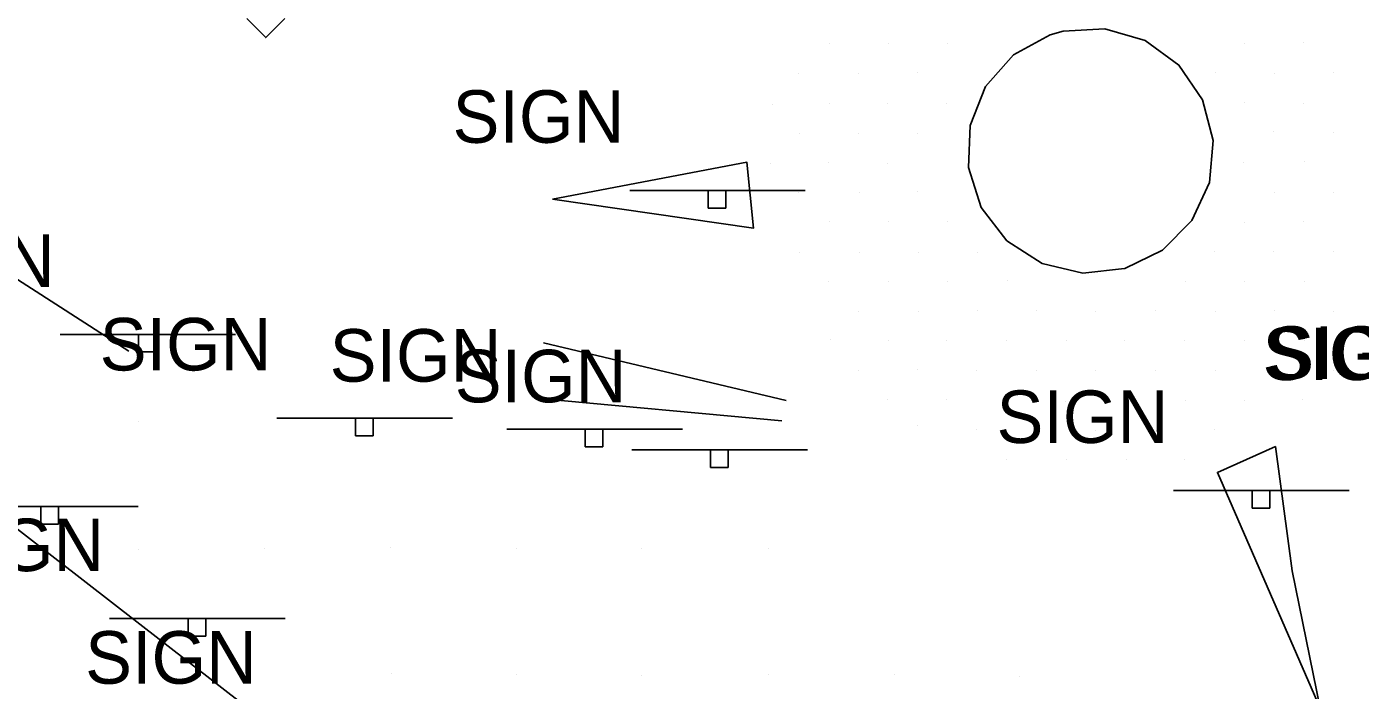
# Model space of a CAD drawing. Extents: x 1602514 to 1609837, y 863887 to 871157.
# Drawn here: x 1604719.6 to 1604878.4, y 866874 to 866952.9 of the extents above; entities that cross this region are included whole.
import ezdxf

# ---------------------------------------------------------------- set-up
doc = ezdxf.new("R2010")
doc.units = 0
for name, color, linetype in [('Environmental-New trees', 7, 'Continuous'), ('Roadway-Signs', 7, 'Continuous'), ('Survey-Centerline', 7, 'Continuous'), ('Survey-Edge of pavement', 7, 'Continuous'), ('Survey-Ridge Lines', 7, 'Continuous'), ('Survey-Shoulders', 7, 'Continuous'), ('Survey-Signs', 7, 'Continuous'), ('Survey-Spot dirt', 7, 'Continuous')]:
    doc.layers.add(name, color=color, linetype=linetype)

msp = doc.modelspace()

# ---------------------------------------------------------------- linework, layer by layer
at = {"layer": 'Environmental-New trees'}
msp.add_lwpolyline([(1604750.35, 866953.9), (1604748.1, 866951.65), (1604745.85, 866953.9)], dxfattribs=at)
msp.add_lwpolyline([(1604750.35, 866953.9), (1604748.1, 866951.65), (1604745.85, 866953.9)], dxfattribs=at)
at = {"layer": 'Roadway-Signs'}
for p, q in [((1604791.41, 866933.46), (1604812.31, 866933.46)), ((1604791.41, 866933.46), (1604812.31, 866933.46)), ((1604800.76, 866931.36), (1604800.76, 866933.46)), ((1604800.76, 866931.36), (1604800.76, 866933.46)), ((1604801.81, 866933.46), (1604801.81, 866933.46)), ((1604801.81, 866933.46), (1604801.81, 866933.46)), ((1604802.86, 866933.46), (1604802.86, 866931.36)), ((1604802.86, 866933.46), (1604802.86, 866931.36)), ((1604802.86, 866931.36), (1604800.76, 866931.36)), ((1604802.86, 866931.36), (1604800.76, 866931.36)), ((1604723.61, 866916.33), (1604744.51, 866916.33)), ((1604723.61, 866916.33), (1604744.51, 866916.33)), ((1604732.96, 866914.23), (1604732.96, 866916.33)), ((1604732.96, 866914.23), (1604732.96, 866916.33)), ((1604734.01, 866916.33), (1604734.01, 866916.33)), ((1604734.01, 866916.33), (1604734.01, 866916.33)), ((1604735.06, 866916.33), (1604735.06, 866914.23)), ((1604735.06, 866916.33), (1604735.06, 866914.23)), ((1604735.06, 866914.23), (1604732.96, 866914.23)), ((1604735.06, 866914.23), (1604732.96, 866914.23)), ((1604749.41, 866906.37), (1604770.31, 866906.37)), ((1604749.41, 866906.37), (1604770.31, 866906.37)), ((1604758.76, 866904.27), (1604758.76, 866906.37)), ((1604758.76, 866904.27), (1604758.76, 866906.37)), ((1604759.81, 866906.37), (1604759.81, 866906.37)), ((1604759.81, 866906.37), (1604759.81, 866906.37)), ((1604760.86, 866906.37), (1604760.86, 866904.27)), ((1604760.86, 866906.37), (1604760.86, 866904.27)), ((1604776.78, 866905.05), (1604797.68, 866905.05)), ((1604776.78, 866905.05), (1604797.68, 866905.05)), ((1604786.13, 866902.95), (1604786.13, 866905.05)), ((1604786.13, 866902.95), (1604786.13, 866905.05)), ((1604787.18, 866905.05), (1604787.18, 866905.05)), ((1604787.18, 866905.05), (1604787.18, 866905.05)), ((1604788.23, 866905.05), (1604788.23, 866902.95)), ((1604788.23, 866905.05), (1604788.23, 866902.95)), ((1604760.86, 866904.27), (1604758.76, 866904.27)), ((1604760.86, 866904.27), (1604758.76, 866904.27)), ((1604788.23, 866902.95), (1604786.13, 866902.95)), ((1604788.23, 866902.95), (1604786.13, 866902.95)), ((1604791.67, 866902.58), (1604812.57, 866902.58)), ((1604791.67, 866902.58), (1604812.57, 866902.58)), ((1604801.02, 866900.48), (1604801.02, 866902.58)), ((1604801.02, 866900.48), (1604801.02, 866902.58)), ((1604802.07, 866902.58), (1604802.07, 866902.58)), ((1604802.07, 866902.58), (1604802.07, 866902.58)), ((1604803.12, 866902.58), (1604803.12, 866900.48)), ((1604803.12, 866902.58), (1604803.12, 866900.48)), ((1604803.12, 866900.48), (1604801.02, 866900.48)), ((1604803.12, 866900.48), (1604801.02, 866900.48)), ((1604856.16, 866897.75), (1604877.06, 866897.75)), ((1604856.16, 866897.75), (1604877.06, 866897.75)), ((1604865.51, 866895.65), (1604865.51, 866897.75)), ((1604865.51, 866895.65), (1604865.51, 866897.75)), ((1604866.56, 866897.75), (1604866.56, 866897.75)), ((1604866.56, 866897.75), (1604866.56, 866897.75)), ((1604867.61, 866897.75), (1604867.61, 866895.65)), ((1604867.61, 866897.75), (1604867.61, 866895.65)), ((1604711.98, 866895.83), (1604732.89, 866895.83)), ((1604711.98, 866895.83), (1604732.89, 866895.83)), ((1604721.34, 866893.73), (1604721.34, 866895.83)), ((1604721.34, 866893.73), (1604721.34, 866895.83)), ((1604722.39, 866895.83), (1604722.39, 866895.83)), ((1604722.39, 866895.83), (1604722.39, 866895.83)), ((1604723.44, 866895.83), (1604723.44, 866893.73)), ((1604723.44, 866895.83), (1604723.44, 866893.73)), ((1604867.61, 866895.65), (1604865.51, 866895.65)), ((1604867.61, 866895.65), (1604865.51, 866895.65)), ((1604723.44, 866893.73), (1604721.34, 866893.73)), ((1604723.44, 866893.73), (1604721.34, 866893.73)), ((1604729.51, 866882.5), (1604750.41, 866882.5)), ((1604729.51, 866882.5), (1604750.41, 866882.5)), ((1604738.86, 866880.4), (1604738.86, 866882.5)), ((1604738.86, 866880.4), (1604738.86, 866882.5)), ((1604739.91, 866882.5), (1604739.91, 866882.5)), ((1604739.91, 866882.5), (1604739.91, 866882.5)), ((1604740.96, 866882.5), (1604740.96, 866880.4)), ((1604740.96, 866882.5), (1604740.96, 866880.4)), ((1604740.96, 866880.4), (1604738.86, 866880.4)), ((1604740.96, 866880.4), (1604738.86, 866880.4))]:
    msp.add_line(p, q, dxfattribs=at)
at = {"layer": 'Survey-Centerline'}
for points in [[(1604850.31, 866924.15), (1604845.35, 866923.59), (1604840.49, 866924.74), (1604836.29, 866927.46), (1604833.26, 866931.43), (1604831.74, 866936.2), (1604831.92, 866941.19), (1604833.77, 866945.83), (1604837.08, 866949.57), (1604841.46, 866951.97), (1604842.99, 866952.41)], [(1604850.31, 866924.15), (1604845.35, 866923.59), (1604840.49, 866924.74), (1604836.29, 866927.46), (1604833.26, 866931.43), (1604831.74, 866936.2), (1604831.92, 866941.19), (1604833.77, 866945.83), (1604837.08, 866949.57), (1604841.46, 866951.97), (1604842.99, 866952.41)], [(1604842.99, 866952.41), (1604847.97, 866952.7), (1604852.75, 866951.3), (1604856.79, 866948.36), (1604859.61, 866944.23), (1604860.87, 866939.39), (1604860.43, 866934.41), (1604858.34, 866929.88), (1604854.85, 866926.33), (1604850.36, 866924.17), (1604850.31, 866924.15)], [(1604842.99, 866952.41), (1604847.97, 866952.7), (1604852.75, 866951.3), (1604856.79, 866948.36), (1604859.61, 866944.23), (1604860.87, 866939.39), (1604860.43, 866934.41), (1604858.34, 866929.88), (1604854.85, 866926.33), (1604850.36, 866924.17), (1604850.31, 866924.15)], [(1604782.22, 866932.4), (1604806.16, 866928.98), (1604805.36, 866936.8), (1604782.22, 866932.4)], [(1604782.22, 866932.4), (1604806.16, 866928.98), (1604805.36, 866936.8), (1604782.22, 866932.4)], [(1604873.59, 866871.86), (1604870.26, 866888.2), (1604868.28, 866902.98), (1604861.37, 866899.9), (1604873.59, 866871.86)], [(1604873.59, 866871.86), (1604870.26, 866888.2), (1604868.28, 866902.98), (1604861.37, 866899.9), (1604873.59, 866871.86)]]:
    msp.add_lwpolyline(points, dxfattribs=at)
at = {"layer": 'Survey-Edge of pavement'}
msp.add_line((1604781.14, 866915.31), (1604810.02, 866908.44), dxfattribs=at)
msp.add_line((1604781.14, 866915.31), (1604810.02, 866908.44), dxfattribs=at)
msp.add_lwpolyline([(1604691.74, 866913.93), (1604754.93, 866864.89), (1604787.98, 866839.79), (1604824.93, 866812.89)], dxfattribs=at)
msp.add_lwpolyline([(1604691.74, 866913.93), (1604754.93, 866864.89), (1604787.98, 866839.79), (1604824.93, 866812.89)], dxfattribs=at)
at = {"layer": 'Survey-Ridge Lines'}
msp.add_lwpolyline([(1604697.31, 866935.97), (1604714.39, 866925.53), (1604731.78, 866914.32)], dxfattribs=at)
msp.add_lwpolyline([(1604697.31, 866935.97), (1604714.39, 866925.53), (1604731.78, 866914.32)], dxfattribs=at)
at = {"layer": 'Survey-Shoulders'}
msp.add_line((1604780.2, 866908.72), (1604809.53, 866906.04), dxfattribs=at)
msp.add_line((1604780.2, 866908.72), (1604809.53, 866906.04), dxfattribs=at)
at = {"layer": 'Survey-Spot dirt'}
for p, q in [((1604815.14, 866950.9), (1604815.14, 866950.9)), ((1604815.14, 866950.9), (1604815.14, 866950.9)), ((1604822.17, 866950.96), (1604822.17, 866950.96)), ((1604822.17, 866950.96), (1604822.17, 866950.96)), ((1604829.28, 866950.96), (1604829.28, 866950.96)), ((1604829.28, 866950.96), (1604829.28, 866950.96)), ((1604864.6, 866950.96), (1604864.6, 866950.96)), ((1604864.6, 866950.96), (1604864.6, 866950.96)), ((1604871.6, 866951), (1604871.6, 866951)), ((1604871.6, 866951), (1604871.6, 866951)), ((1604811.5, 866947.39), (1604811.5, 866947.39)), ((1604811.5, 866947.39), (1604811.5, 866947.39)), ((1604818.64, 866947.4), (1604818.64, 866947.4)), ((1604818.64, 866947.4), (1604818.64, 866947.4)), ((1604825.63, 866947.47), (1604825.63, 866947.47)), ((1604825.63, 866947.47), (1604825.63, 866947.47)), ((1604861.1, 866947.45), (1604861.1, 866947.45)), ((1604861.1, 866947.45), (1604861.1, 866947.45)), ((1604868.14, 866947.42), (1604868.14, 866947.42)), ((1604868.14, 866947.42), (1604868.14, 866947.42)), ((1604875.16, 866947.48), (1604875.16, 866947.48)), ((1604875.16, 866947.48), (1604875.16, 866947.48)), ((1604808.41, 866943.69), (1604808.41, 866943.69)), ((1604808.41, 866943.69), (1604808.41, 866943.69)), ((1604815.19, 866943.75), (1604815.19, 866943.75)), ((1604815.19, 866943.75), (1604815.19, 866943.75)), ((1604822.12, 866943.85), (1604822.12, 866943.85)), ((1604822.12, 866943.85), (1604822.12, 866943.85)), ((1604829.18, 866943.83), (1604829.18, 866943.83)), ((1604829.18, 866943.83), (1604829.18, 866943.83)), ((1604864.56, 866943.86), (1604864.56, 866943.86)), ((1604864.56, 866943.86), (1604864.56, 866943.86)), ((1604871.67, 866943.82), (1604871.67, 866943.82)), ((1604871.67, 866943.82), (1604871.67, 866943.82)), ((1604811.59, 866940.23), (1604811.59, 866940.23)), ((1604811.59, 866940.23), (1604811.59, 866940.23)), ((1604818.65, 866940.22), (1604818.65, 866940.22)), ((1604818.65, 866940.22), (1604818.65, 866940.22)), ((1604825.66, 866940.23), (1604825.66, 866940.23)), ((1604825.66, 866940.23), (1604825.66, 866940.23)), ((1604868.08, 866940.41), (1604868.08, 866940.41)), ((1604868.08, 866940.41), (1604868.08, 866940.41)), ((1604875.18, 866940.35), (1604875.18, 866940.35)), ((1604875.18, 866940.35), (1604875.18, 866940.35)), ((1604808.16, 866936.7), (1604808.16, 866936.7)), ((1604808.16, 866936.7), (1604808.16, 866936.7)), ((1604815.1, 866936.77), (1604815.1, 866936.77)), ((1604815.1, 866936.77), (1604815.1, 866936.77)), ((1604822.12, 866936.69), (1604822.12, 866936.69)), ((1604822.12, 866936.69), (1604822.12, 866936.69)), ((1604864.52, 866936.81), (1604864.52, 866936.81)), ((1604864.52, 866936.81), (1604864.52, 866936.81)), ((1604871.69, 866936.87), (1604871.69, 866936.87)), ((1604871.69, 866936.87), (1604871.69, 866936.87)), ((1604811.52, 866933.21), (1604811.52, 866933.21)), ((1604811.52, 866933.21), (1604811.52, 866933.21)), ((1604818.75, 866933.24), (1604818.75, 866933.24)), ((1604818.75, 866933.24), (1604818.75, 866933.24)), ((1604825.65, 866933.27), (1604825.65, 866933.27)), ((1604825.65, 866933.27), (1604825.65, 866933.27)), ((1604868.16, 866933.24), (1604868.16, 866933.24)), ((1604868.16, 866933.24), (1604868.16, 866933.24)), ((1604875.22, 866933.24), (1604875.22, 866933.24)), ((1604875.22, 866933.24), (1604875.22, 866933.24)), ((1604815.2, 866929.75), (1604815.2, 866929.75)), ((1604815.2, 866929.75), (1604815.2, 866929.75)), ((1604822.18, 866929.7), (1604822.18, 866929.7)), ((1604822.18, 866929.7), (1604822.18, 866929.7)), ((1604829.23, 866929.76), (1604829.23, 866929.76)), ((1604829.23, 866929.76), (1604829.23, 866929.76)), ((1604871.65, 866929.72), (1604871.65, 866929.72)), ((1604871.65, 866929.72), (1604871.65, 866929.72)), ((1604864.59, 866929.66), (1604864.59, 866929.66)), ((1604864.59, 866929.66), (1604864.59, 866929.66)), ((1604811.63, 866926.1), (1604811.63, 866926.1)), ((1604811.63, 866926.1), (1604811.63, 866926.1)), ((1604818.72, 866926.08), (1604818.72, 866926.08)), ((1604818.72, 866926.08), (1604818.72, 866926.08)), ((1604825.78, 866926.12), (1604825.78, 866926.12)), ((1604825.78, 866926.12), (1604825.78, 866926.12)), ((1604832.77, 866926.12), (1604832.77, 866926.12)), ((1604832.77, 866926.12), (1604832.77, 866926.12)), ((1604861.01, 866926.21), (1604861.01, 866926.21)), ((1604861.01, 866926.21), (1604861.01, 866926.21)), ((1604868.04, 866926.17), (1604868.04, 866926.17)), ((1604868.04, 866926.17), (1604868.04, 866926.17)), ((1604875.18, 866926.14), (1604875.18, 866926.14)), ((1604875.18, 866926.14), (1604875.18, 866926.14)), ((1604815.08, 866922.59), (1604815.08, 866922.59)), ((1604815.08, 866922.59), (1604815.08, 866922.59)), ((1604822.18, 866922.63), (1604822.18, 866922.63)), ((1604822.18, 866922.63), (1604822.18, 866922.63)), ((1604829.23, 866922.59), (1604829.23, 866922.59)), ((1604829.23, 866922.59), (1604829.23, 866922.59)), ((1604836.33, 866922.69), (1604836.33, 866922.69)), ((1604836.33, 866922.69), (1604836.33, 866922.69)), ((1604857.58, 866922.62), (1604857.58, 866922.62)), ((1604857.58, 866922.62), (1604857.58, 866922.62)), ((1604864.59, 866922.57), (1604864.59, 866922.57)), ((1604864.59, 866922.57), (1604864.59, 866922.57)), ((1604871.75, 866922.57), (1604871.75, 866922.57)), ((1604871.75, 866922.57), (1604871.75, 866922.57)), ((1604818.62, 866919.03), (1604818.62, 866919.03)), ((1604818.62, 866919.03), (1604818.62, 866919.03)), ((1604825.75, 866919.09), (1604825.75, 866919.09)), ((1604825.75, 866919.09), (1604825.75, 866919.09)), ((1604832.78, 866919.13), (1604832.78, 866919.13)), ((1604832.78, 866919.13), (1604832.78, 866919.13)), ((1604839.8, 866919.12), (1604839.8, 866919.12)), ((1604839.8, 866919.12), (1604839.8, 866919.12)), ((1604846.9, 866919.1), (1604846.9, 866919.1)), ((1604846.9, 866919.1), (1604846.9, 866919.1)), ((1604853.99, 866919.12), (1604853.99, 866919.12)), ((1604853.99, 866919.12), (1604853.99, 866919.12)), ((1604861.17, 866919.06), (1604861.17, 866919.06)), ((1604861.17, 866919.06), (1604861.17, 866919.06)), ((1604868.16, 866919.13), (1604868.16, 866919.13)), ((1604868.16, 866919.13), (1604868.16, 866919.13)), ((1604875.23, 866919.1), (1604875.23, 866919.1)), ((1604875.23, 866919.1), (1604875.23, 866919.1)), ((1604815.33, 866915.66), (1604815.33, 866915.66)), ((1604815.33, 866915.66), (1604815.33, 866915.66)), ((1604822.18, 866915.61), (1604822.18, 866915.61)), ((1604822.18, 866915.61), (1604822.18, 866915.61)), ((1604829.15, 866915.65), (1604829.15, 866915.65)), ((1604829.15, 866915.65), (1604829.15, 866915.65)), ((1604836.3, 866915.64), (1604836.3, 866915.64)), ((1604836.3, 866915.64), (1604836.3, 866915.64)), ((1604843.36, 866915.56), (1604843.36, 866915.56)), ((1604843.36, 866915.56), (1604843.36, 866915.56)), ((1604850.36, 866915.57), (1604850.36, 866915.57)), ((1604850.36, 866915.57), (1604850.36, 866915.57)), ((1604857.43, 866915.54), (1604857.43, 866915.54)), ((1604857.43, 866915.54), (1604857.43, 866915.54)), ((1604864.62, 866915.62), (1604864.62, 866915.62)), ((1604864.62, 866915.62), (1604864.62, 866915.62)), ((1604871.68, 866915.61), (1604871.68, 866915.61)), ((1604871.68, 866915.61), (1604871.68, 866915.61)), ((1604818.61, 866912), (1604818.61, 866912)), ((1604818.61, 866912), (1604818.61, 866912)), ((1604825.69, 866912.18), (1604825.69, 866912.18)), ((1604825.69, 866912.18), (1604825.69, 866912.18)), ((1604832.75, 866912.08), (1604832.75, 866912.08)), ((1604832.75, 866912.08), (1604832.75, 866912.08)), ((1604839.8, 866912.07), (1604839.8, 866912.07)), ((1604839.8, 866912.07), (1604839.8, 866912.07)), ((1604846.86, 866911.97), (1604846.86, 866911.97)), ((1604846.86, 866911.97), (1604846.86, 866911.97)), ((1604853.97, 866912.05), (1604853.97, 866912.05)), ((1604853.97, 866912.05), (1604853.97, 866912.05)), ((1604861.09, 866912.04), (1604861.09, 866912.04)), ((1604861.09, 866912.04), (1604861.09, 866912.04)), ((1604868.12, 866912.05), (1604868.12, 866912.05)), ((1604868.12, 866912.05), (1604868.12, 866912.05)), ((1604875.16, 866912.02), (1604875.16, 866912.02)), ((1604875.16, 866912.02), (1604875.16, 866912.02)), ((1604822.14, 866908.58), (1604822.14, 866908.58)), ((1604822.14, 866908.58), (1604822.14, 866908.58)), ((1604829.14, 866908.6), (1604829.14, 866908.6)), ((1604829.14, 866908.6), (1604829.14, 866908.6)), ((1604836.28, 866908.51), (1604836.28, 866908.51)), ((1604836.28, 866908.51), (1604836.28, 866908.51)), ((1604843.25, 866908.38), (1604843.25, 866908.38)), ((1604843.25, 866908.38), (1604843.25, 866908.38)), ((1604850.55, 866908.46), (1604850.55, 866908.46)), ((1604850.55, 866908.46), (1604850.55, 866908.46)), ((1604857.61, 866908.48), (1604857.61, 866908.48)), ((1604857.61, 866908.48), (1604857.61, 866908.48)), ((1604864.59, 866908.42), (1604864.59, 866908.42)), ((1604864.59, 866908.42), (1604864.59, 866908.42)), ((1604871.55, 866908.56), (1604871.55, 866908.56)), ((1604871.55, 866908.56), (1604871.55, 866908.56)), ((1604732.98, 866905.92), (1604732.98, 866905.92)), ((1604732.98, 866905.92), (1604732.98, 866905.92)), ((1604825.71, 866905.53), (1604825.71, 866905.53)), ((1604825.71, 866905.53), (1604825.71, 866905.53)), ((1604832.68, 866904.99), (1604832.68, 866904.99)), ((1604832.68, 866904.99), (1604832.68, 866904.99)), ((1604839.84, 866904.95), (1604839.84, 866904.95)), ((1604839.84, 866904.95), (1604839.84, 866904.95)), ((1604846.91, 866904.92), (1604846.91, 866904.92)), ((1604846.91, 866904.92), (1604846.91, 866904.92)), ((1604854.07, 866904.94), (1604854.07, 866904.94)), ((1604854.07, 866904.94), (1604854.07, 866904.94)), ((1604861.07, 866905), (1604861.07, 866905)), ((1604861.07, 866905), (1604861.07, 866905)), ((1604836.28, 866901.46), (1604836.28, 866901.46)), ((1604836.28, 866901.46), (1604836.28, 866901.46)), ((1604843.36, 866901.49), (1604843.36, 866901.49)), ((1604843.36, 866901.49), (1604843.36, 866901.49)), ((1604850.51, 866901.46), (1604850.51, 866901.46)), ((1604850.51, 866901.46), (1604850.51, 866901.46)), ((1604857.48, 866901.39), (1604857.48, 866901.39)), ((1604857.48, 866901.39), (1604857.48, 866901.39)), ((1604732.93, 866890.75), (1604732.93, 866890.75)), ((1604732.93, 866890.75), (1604732.93, 866890.75)), ((1604747.97, 866890.86), (1604747.97, 866890.86)), ((1604747.97, 866890.86), (1604747.97, 866890.86)), ((1604762.89, 866890.92), (1604762.89, 866890.92)), ((1604762.89, 866890.92), (1604762.89, 866890.92)), ((1604777.97, 866890.84), (1604777.97, 866890.84)), ((1604777.97, 866890.84), (1604777.97, 866890.84)), ((1604792.84, 866890.86), (1604792.84, 866890.86)), ((1604792.84, 866890.86), (1604792.84, 866890.86)), ((1604807.93, 866890.85), (1604807.93, 866890.85)), ((1604807.93, 866890.85), (1604807.93, 866890.85)), ((1604763.01, 866875.93), (1604763.01, 866875.93)), ((1604763.01, 866875.93), (1604763.01, 866875.93)), ((1604777.93, 866875.89), (1604777.93, 866875.89)), ((1604777.93, 866875.89), (1604777.93, 866875.89)), ((1604792.81, 866875.79), (1604792.81, 866875.79)), ((1604792.81, 866875.79), (1604792.81, 866875.79)), ((1604807.95, 866875.86), (1604807.95, 866875.86)), ((1604807.95, 866875.86), (1604807.95, 866875.86)), ((1604822.95, 866875.8), (1604822.95, 866875.8)), ((1604822.95, 866875.8), (1604822.95, 866875.8)), ((1604837.77, 866875.65), (1604837.77, 866875.65)), ((1604837.77, 866875.65), (1604837.77, 866875.65))]:
    msp.add_line(p, q, dxfattribs=at)

# ---------------------------------------------------------------- texts
at = {"layer": 'Roadway-Signs'}
for p in [(1604770.33, 866939.12), (1604770.33, 866939.12), (1604702.53, 866921.98), (1604702.53, 866921.98), (1604728.33, 866912.03), (1604728.33, 866912.03), (1604755.7, 866910.7), (1604755.7, 866910.7), (1604867.3, 866911.03), (1604867.3, 866911.03), (1604770.59, 866908.24), (1604770.59, 866908.24), (1604835.08, 866903.4), (1604835.08, 866903.4), (1604708.43, 866888.15), (1604708.43, 866888.15), (1604726.6, 866874.76), (1604726.6, 866874.76)]:
    msp.add_text('SIGN', height=6.25, dxfattribs=at).set_placement(p)
at = {"layer": 'Survey-Signs'}
msp.add_text('SIGN', height=6.25, rotation=360, dxfattribs=at).set_placement((1604866.74, 866910.89))

doc.saveas('drawing.dxf')
